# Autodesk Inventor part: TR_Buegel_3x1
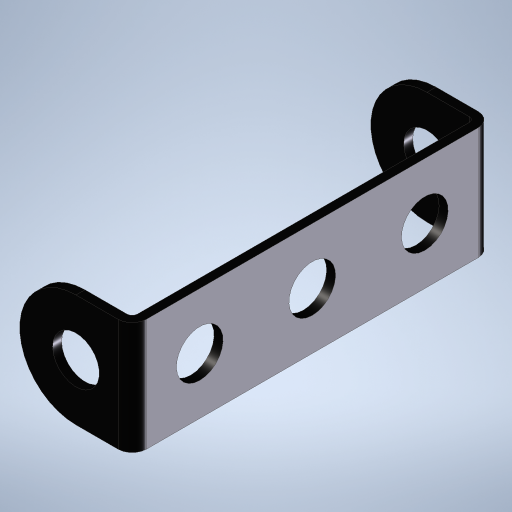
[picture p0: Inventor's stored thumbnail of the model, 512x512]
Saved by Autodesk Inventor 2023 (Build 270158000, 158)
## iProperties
Created: 2023-11
Part Number: TR_Buegel_3x1
Material: Edelstahl
Document SubType Name: Modeling
Designer: Admin
Density: 8 g/cm^3
Appearance: Halbpoliert
Author: Admin
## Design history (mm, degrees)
sketch "Skizze1"
  geometry: L1 (10, 16)-(1.25, 16); L2 (0, 14.75)-(0, -14.75); L3 (1.25, -16)-(10, -16); L4 (10, -16)-(10, -15.2); L5 (10, -15.2)-(1.25, -15.2); L6 (0.8, -14.75)-(0.8, 14.75); L7 (1.25, 15.2)-(10, 15.2); L8 (10, 15.2)-(10, 16); A1 r 1.25 centre (1.25, 14.75) between (1.25, 16) and (0, 14.75); A2 r 1.25 centre (1.25, -14.75) between (0, -14.75) and (1.25, -16); A3 r 0.45 centre (1.25, 14.75) between (1.25, 15.2) and (0.8, 14.75); A4 r 0.45 centre (1.25, -14.75) between (0.8, -14.75) and (1.25, -15.2); 5 further points
  constraints: 16 end point, 8 point on circle, 8 tangent, 4 centre point, 4 point on line, 3 horizontal, 3 perpendicular, 2 equal radius, 2 midpoint, 2 vertical alignment, 1 coincident, 1 collinear, 1 horizontal alignment, 1 parallel, 1 vertical
  dimensions: "d0" = 0.8 distance of L7.end L1.start (= Dicke); "d1" = 10 horizontal distance of point (0, 0) L1.start (= Einheitsmaß); "d2" = 0.8 horizontal distance of point (0, 0) point (0.8, 15.2) (= Dicke); "d6" = 1.25 radius of A1; "d7" = 32 distance of L3.end L1.start
extrude "Extrusion1" new body sketch "Skizze1" stored distance "d8" = 10 (= Einheitsmaß); taper "d9" = 0 deg
fillet "Rundung1" dims "d10" = 5 (= 0.5 x Einheitsmaß)
sketch "Skizze2"
  geometry: C1 r 2.075 at (-5, 0); A1 r 5 centre (-5, 0) between (-5, 5) and (-5, -5) reference; 1 further point
  constraints: 1 centre point, 1 coincident
  dimensions: "d11" = 4.15 diameter of C1 (= 2 x Radius)
extrude "Extrusion2" cut sketch "Skizze2" extent not by distance; stored distance "d12" = 0; taper "d13" = 0 deg
sketch "Skizze3"
  geometry: C1 r 2.075 at (0, 0); 1 further point
  constraints: 1 centre point, 1 coincident
  dimensions: "d14" = 4.15 diameter of C1 (= 2 x Radius)
extrude "Extrusion3" cut sketch "Skizze3" extent not by distance; stored distance "d15" = 0; taper "d16" = 0 deg
pattern_linear "Rechteckige Anordnung2" dims "d22" = 10 (= Einheitsmaß)
node "Volumenkörper1"
other parameters: "Einheitsmaß" = 10 [user parameter; used in 4 equation terms], "Radius" = 2.075 [user parameter; used in 2 equation terms], "Fasen" = 0.5 [user parameter], "Dicke" = 0.8 [user parameter; used in 2 equation terms]
